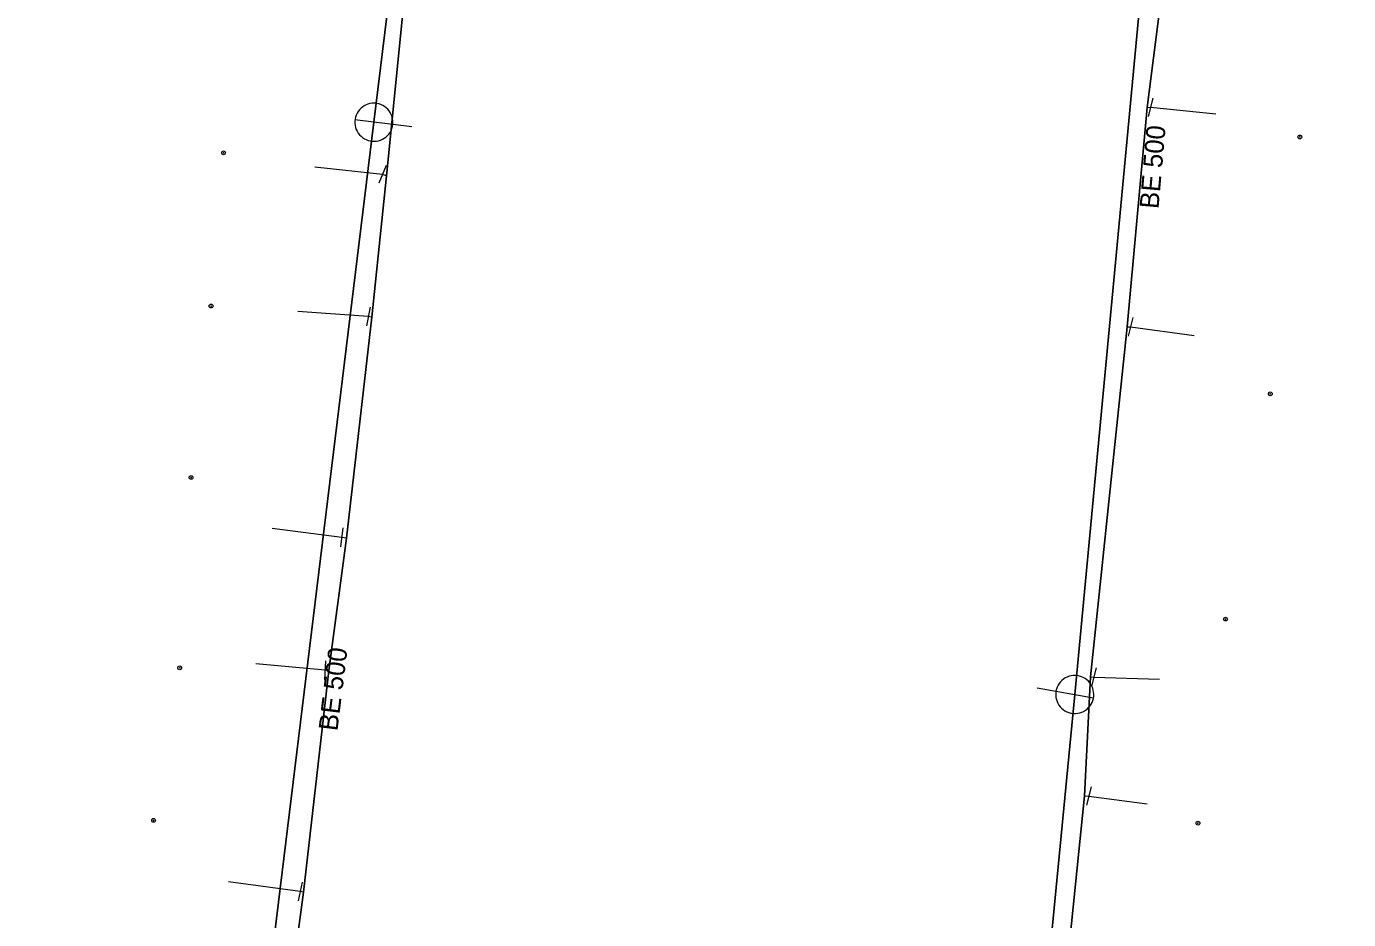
# Model space of a CAD drawing. Extents: x -783064 to -782702, y -1007904 to -1007145.
# Drawn here: x -782930.5 to -782861.1, y -1007289.3 to -1007242.4 of the extents above; entities that cross this region are included whole.
import ezdxf

# ---------------------------------------------------------------- set-up
doc = ezdxf.new("R2010")
doc.units = 0
doc.header["$LTSCALE"] = 0.4
doc.header["$PDMODE"] = 32
doc.header["$PDSIZE"] = 0.2
for name, color, linetype, lineweight in [('1', 7, 'Continuous', 13), ('13', 7, 'Continuous', 13), ('14', 7, 'Continuous', 13), ('17', 7, 'Continuous', 25), ('22', 7, 'Continuous', 13), ('34', 7, 'Continuous', 13)]:
    doc.layers.add(name, color=color, linetype=linetype, lineweight=lineweight)

msp = doc.modelspace()

# ---------------------------------------------------------------- linework, layer by layer
at = {"layer": '1'}
for p in [(-782863.64, -1007248.239), (-782920.17, -1007249.069), (-782920.82, -1007257.119), (-782865.19, -1007261.729), (-782921.87, -1007266.119), (-782867.539, -1007273.559), (-782922.469, -1007276.119), (-782923.84, -1007284.129), (-782868.989, -1007284.279)]:
    msp.add_point(p, dxfattribs=at)
at = {"layer": '13'}
for p, q in [((-782871.485, -1007246.68), (-782868.055, -1007247.027)), ((-782911.816, -1007250.204), (-782915.372, -1007249.832)), ((-782912.564, -1007257.661), (-782916.256, -1007257.413)), ((-782872.528, -1007258.209), (-782869.184, -1007258.657)), ((-782913.96, -1007269.272), (-782917.614, -1007268.805)), ((-782914.834, -1007276.243), (-782918.467, -1007275.902)), ((-782874.454, -1007276.607), (-782871.004, -1007276.722)), ((-782874.717, -1007282.852), (-782871.66, -1007283.262)), ((-782916.136, -1007287.858), (-782919.912, -1007287.355))]:
    msp.add_line(p, q, dxfattribs=at)
at = {"layer": '14'}
for p, q in [((-782871.656, -1007246.694), (-782871.485, -1007246.68)), ((-782911.614, -1007250.289), (-782911.816, -1007250.204)), ((-782912.373, -1007257.698), (-782912.564, -1007257.661)), ((-782872.715, -1007258.202), (-782872.528, -1007258.209)), ((-782913.715, -1007269.301), (-782913.96, -1007269.272)), ((-782914.642, -1007276.256), (-782914.834, -1007276.243)), ((-782874.627, -1007276.587), (-782874.454, -1007276.607)), ((-782874.949, -1007282.841), (-782874.717, -1007282.852)), ((-782915.969, -1007287.894), (-782916.136, -1007287.858))]:
    msp.add_line(p, q, dxfattribs=at)
at = {"layer": '14', "lineweight": 25}
msp.add_line((-782881.64, -1007341.74), (-782875.46, -1007277.52), dxfattribs=at)
for points in [[(-782912.27, -1007247.465), (-782909.037, -1007221.044), (-782908.162, -1007213.894), (-782907.03, -1007204.64)], [(-782875.46, -1007277.52), (-782870.059, -1007220.221), (-782861.079, -1007216.63)], [(-782930.292, -1007394.745), (-782924.885, -1007350.562), (-782919.554, -1007306.995), (-782919.314, -1007305.034), (-782912.27, -1007247.465)]]:
    msp.add_lwpolyline(points, dxfattribs=at)
at = {"layer": '17'}
for points in [[(-782929.875, -1007401.245), (-782929.734, -1007399.601), (-782930.517, -1007396.682), (-782929.522, -1007392.415), (-782928.77, -1007388.515), (-782924.138, -1007354.049), (-782922.885, -1007342.946), (-782921.559, -1007334.301), (-782920.563, -1007323.904), (-782919.227, -1007312.942), (-782917.886, -1007302.487), (-782916.995, -1007295.62), (-782915.969, -1007287.894), (-782914.642, -1007276.256), (-782913.715, -1007269.301), (-782912.373, -1007257.698), (-782911.614, -1007250.289), (-782910.5, -1007239.254), (-782909.879, -1007233.809), (-782906.177, -1007206.061), (-782905.546, -1007203.154), (-782904.197, -1007194.592), (-782903.806, -1007194.072)], [(-782865.873, -1007217.55), (-782867.1, -1007219.872), (-782868.296, -1007223.249), (-782869.76, -1007231.842), (-782871.656, -1007246.694), (-782872.715, -1007258.202), (-782874.627, -1007276.587), (-782874.949, -1007282.841), (-782876.037, -1007293.495), (-782876.995, -1007303.315), (-782877.686, -1007309.964), (-782878.971, -1007323.201), (-782879.489, -1007327.875), (-782880.28, -1007336.799), (-782881.43, -1007348.813), (-782882.258, -1007357.662), (-782883.206, -1007365.599), (-782883.811, -1007372.562), (-782883.988, -1007373.804), (-782884.406, -1007378.793), (-782885.879, -1007397.825), (-782886.204, -1007402.774), (-782886.721, -1007407.932)]]:
    msp.add_lwpolyline(points, dxfattribs=at)
at = {"layer": '22'}
for p, q in [((-782910.284, -1007247.707), (-782913.262, -1007247.343)), ((-782877.43, -1007277.172), (-782874.475, -1007277.693))]:
    msp.add_line(p, q, dxfattribs=at)
for points in [[(-782912.148, -1007246.472), (-782912.256, -1007246.465), (-782912.366, -1007246.469), (-782912.475, -1007246.486), (-782912.58, -1007246.514), (-782912.682, -1007246.554), (-782912.779, -1007246.604), (-782912.87, -1007246.666), (-782912.954, -1007246.736), (-782913.03, -1007246.815), (-782913.096, -1007246.902), (-782913.153, -1007246.996), (-782913.198, -1007247.096), (-782913.233, -1007247.2), (-782913.256, -1007247.307), (-782913.267, -1007247.416), (-782913.267, -1007247.525), (-782913.255, -1007247.634), (-782913.231, -1007247.741), (-782913.194, -1007247.844), (-782913.148, -1007247.942), (-782913.089, -1007248.036), (-782913.022, -1007248.122), (-782912.945, -1007248.201), (-782912.861, -1007248.271), (-782912.77, -1007248.33), (-782912.672, -1007248.379), (-782912.569, -1007248.418), (-782912.464, -1007248.445), (-782912.355, -1007248.461), (-782912.245, -1007248.464), (-782912.136, -1007248.456), (-782912.029, -1007248.435), (-782911.924, -1007248.403), (-782911.823, -1007248.36), (-782911.728, -1007248.305), (-782911.64, -1007248.242), (-782911.558, -1007248.168), (-782911.486, -1007248.086), (-782911.422, -1007247.997), (-782911.369, -1007247.901), (-782911.327, -1007247.8), (-782911.296, -1007247.695), (-782911.277, -1007247.587), (-782911.269, -1007247.478), (-782911.274, -1007247.369), (-782911.29, -1007247.261), (-782911.318, -1007247.155), (-782911.358, -1007247.052), (-782911.409, -1007246.955), (-782911.469, -1007246.864), (-782911.539, -1007246.78), (-782911.619, -1007246.705), (-782911.705, -1007246.638), (-782911.799, -1007246.582), (-782911.898, -1007246.536), (-782912.003, -1007246.501), (-782912.11, -1007246.478)], [(-782875.634, -1007278.504), (-782875.525, -1007278.517), (-782875.416, -1007278.518), (-782875.306, -1007278.507), (-782875.2, -1007278.485), (-782875.095, -1007278.451), (-782874.996, -1007278.405), (-782874.902, -1007278.349), (-782874.815, -1007278.283), (-782874.735, -1007278.208), (-782874.664, -1007278.125), (-782874.602, -1007278.034), (-782874.552, -1007277.936), (-782874.511, -1007277.835), (-782874.483, -1007277.729), (-782874.465, -1007277.621), (-782874.46, -1007277.512), (-782874.467, -1007277.402), (-782874.485, -1007277.294), (-782874.516, -1007277.189), (-782874.557, -1007277.089), (-782874.61, -1007276.992), (-782874.673, -1007276.903), (-782874.746, -1007276.82), (-782874.826, -1007276.746), (-782874.914, -1007276.681), (-782875.009, -1007276.627), (-782875.11, -1007276.583), (-782875.214, -1007276.55), (-782875.322, -1007276.529), (-782875.431, -1007276.52), (-782875.54, -1007276.522), (-782875.648, -1007276.538), (-782875.755, -1007276.564), (-782875.858, -1007276.601), (-782875.956, -1007276.651), (-782876.047, -1007276.71), (-782876.133, -1007276.779), (-782876.209, -1007276.857), (-782876.277, -1007276.943), (-782876.335, -1007277.036), (-782876.383, -1007277.134), (-782876.42, -1007277.237), (-782876.445, -1007277.345), (-782876.458, -1007277.453), (-782876.459, -1007277.563), (-782876.448, -1007277.671), (-782876.426, -1007277.779), (-782876.391, -1007277.883), (-782876.346, -1007277.983), (-782876.29, -1007278.077), (-782876.225, -1007278.164), (-782876.149, -1007278.244), (-782876.066, -1007278.315), (-782875.976, -1007278.376), (-782875.879, -1007278.427), (-782875.776, -1007278.468), (-782875.671, -1007278.497)]]:
    msp.add_lwpolyline(points, close=True, dxfattribs=at)
at = {"layer": '34'}
for p, q in [((-782871.359, -1007246.195), (-782871.611, -1007247.163)), ((-782911.625, -1007249.741), (-782912.007, -1007250.665)), ((-782912.469, -1007257.169), (-782912.659, -1007258.151)), ((-782872.402, -1007257.724), (-782872.654, -1007258.692)), ((-782913.903, -1007268.775), (-782914.017, -1007269.768)), ((-782914.803, -1007275.743), (-782914.865, -1007276.742)), ((-782874.328, -1007276.122), (-782874.58, -1007277.09)), ((-782874.591, -1007282.367), (-782874.843, -1007283.335)), ((-782916.033, -1007287.368), (-782916.239, -1007288.347))]:
    msp.add_line(p, q, dxfattribs=at)

# ---------------------------------------------------------------- texts
at = {"layer": '1'}
for rotation, p in [(85, (-782871.063, -1007252.042)), (83, (-782914.186, -1007279.468))]:
    msp.add_text('BE 500', height=1, rotation=rotation, dxfattribs=at).set_placement(p)

doc.saveas('drawing.dxf')
